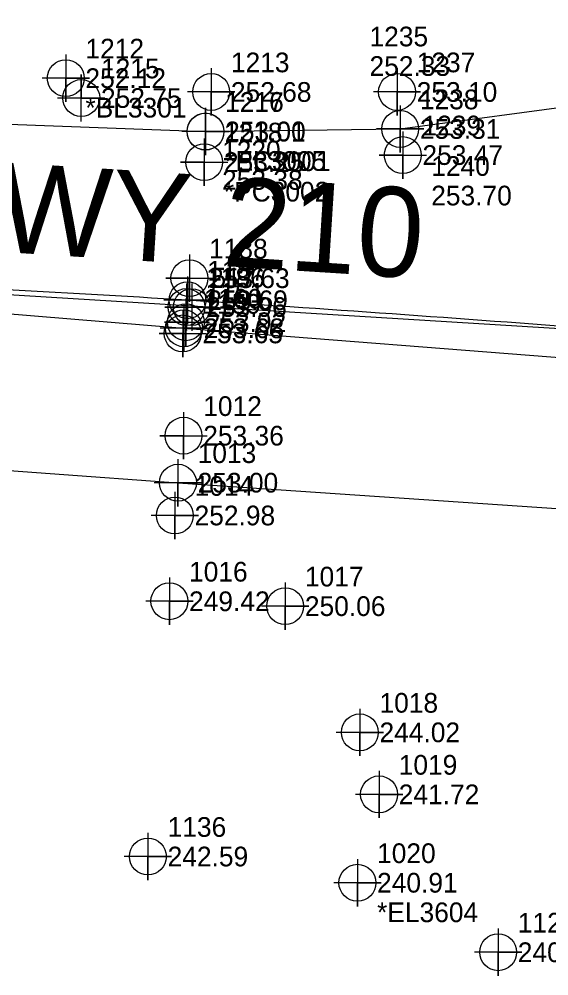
# Model space of a CAD drawing. Extents: x 2130621 to 2131998, y 642516 to 644503.
# Drawn here: x 2131075.1 to 2131142.4, y 643103 to 643224.5 of the extents above; entities that cross this region are included whole.
import ezdxf

# ---------------------------------------------------------------- set-up
doc = ezdxf.new("R2010")
doc.units = 0
for name, color, linetype in [('Cogo Default Point CELL', 7, 'Continuous'), ('COGO Default Point Number', 7, 'Continuous'), ('Exist Guardrail Cogo Comment', 7, 'Continuous'), ('Exist Guardrail Cogo Elevation', 7, 'Continuous'), ('Exist Guardrail Cogo Number', 7, 'Continuous'), ('Exist Guardrail Cogo Point CELL', 7, 'Continuous'), ('Exist Other Culture Fence Line Cogo Elevation', 7, 'Continuous'), ('Exist Other Culture Fence Line Cogo Number', 7, 'Continuous'), ('Exist Other Culture Fence Line Cogo Point CELL', 7, 'Continuous'), ('Exist Other Culture Sign Cogo Elevation', 7, 'Continuous'), ('Exist Other Culture Sign Cogo Number', 7, 'Continuous'), ('Exist Roads Curbs Cogo Elevation', 7, 'Continuous'), ('Exist Roads Curbs Cogo Number', 7, 'Continuous'), ('Exist Roads Curbs Cogo Point CELL', 7, 'Continuous'), ('Exist Roads EOP', 7, 'Continuous'), ('Exist Roads EOP Cogo Comment', 7, 'Continuous'), ('Exist Roads EOP Cogo Elevation', 7, 'Continuous'), ('Exist Roads EOP Cogo Number', 7, 'Continuous'), ('Exist Roads EOP Cogo Point CELL', 7, 'Continuous'), ('Exist Roads EOT Cogo Comment', 7, 'Continuous'), ('Exist Roads EOT Cogo Elevation', 7, 'Continuous'), ('Exist Roads EOT Cogo Number', 7, 'Continuous'), ('Exist Roads EOT Cogo Point CELL', 7, 'Continuous'), ('Exist Roads EOT Text', 7, 'Continuous'), ('Exist Roads Soil Cogo Comment', 7, 'Continuous'), ('Exist Roads Soil Cogo Elevation', 7, 'Continuous'), ('Exist Roads Soil Cogo Number', 7, 'Continuous'), ('Exist Roads Soil Cogo Point CELL', 7, 'Continuous'), ('Exist Vegetation Woods Line Cogo Comment', 7, 'Continuous'), ('Exist Vegetation Woods Line Cogo Elevation', 7, 'Continuous'), ('Exist Vegetation Woods Line Cogo Number', 7, 'Continuous'), ('Exist Vegetation Woods Line Cogo Point CELL', 7, 'Continuous'), ('Prop Horizontal Alignment', 7, 'Continuous')]:
    doc.layers.add(name, color=color, linetype=linetype)

msp = doc.modelspace()

# ---------------------------------------------------------------- linework, layer by layer
at = {"layer": 'Cogo Default Point CELL'}
for points in [[(2131097.03, 643190.9), (2131097.03, 643187.9)], [(2131094.03, 643187.9), (2131097.03, 643187.9)], [(2131097.03, 643187.9), (2131100.03, 643187.9)], [(2131097.03, 643187.9), (2131097.03, 643184.9)]]:
    msp.add_lwpolyline(points, dxfattribs=at)
msp.add_circle((2131097.03, 643187.9), 2.34, dxfattribs=at)
at = {"layer": 'Exist Guardrail Cogo Point CELL'}
for points in [[(2131081.04, 643219.97), (2131081.04, 643213.97), (2131081.04, 643216.97), (2131084.04, 643216.97), (2131078.04, 643216.97)], [(2131099.5, 643218.22), (2131099.5, 643212.22), (2131099.5, 643215.22), (2131102.5, 643215.22), (2131096.5, 643215.22)], [(2131123.08, 643218.22), (2131123.08, 643212.22), (2131123.08, 643215.22), (2131126.08, 643215.22), (2131120.08, 643215.22)], [(2131094.89, 643164.46), (2131094.89, 643158.46), (2131094.89, 643161.46), (2131097.89, 643161.46), (2131091.89, 643161.46)]]:
    msp.add_lwpolyline(points, dxfattribs=at)
for centre in [(2131081.04, 643216.97), (2131099.5, 643215.22), (2131123.08, 643215.22), (2131094.89, 643161.46)]:
    msp.add_circle(centre, 2.34, dxfattribs=at)
at = {"layer": 'Exist Other Culture Fence Line Cogo Point CELL'}
for points in [[(2131091.47, 643121.17), (2131091.47, 643115.17), (2131091.47, 643118.17), (2131094.47, 643118.17), (2131088.47, 643118.17)], [(2131135.91, 643109.02), (2131135.91, 643103.02), (2131135.91, 643106.02), (2131138.91, 643106.02), (2131132.91, 643106.02)]]:
    msp.add_lwpolyline(points, dxfattribs=at)
for centre in [(2131091.47, 643118.17), (2131135.91, 643106.02)]:
    msp.add_circle(centre, 2.34, dxfattribs=at)
at = {"layer": 'Exist Roads Curbs Cogo Point CELL'}
for points in [[(2131096.36, 643190.92), (2131096.36, 643184.92), (2131096.36, 643187.92), (2131093.63, 643187.92), (2131099.36, 643187.92)], [(2131096.29, 643188.99), (2131096.29, 643182.99), (2131096.29, 643185.99), (2131093.56, 643185.99), (2131099.29, 643185.99)]]:
    msp.add_lwpolyline(points, dxfattribs=at)
for centre in [(2131096.36, 643187.92), (2131096.29, 643185.99)]:
    msp.add_circle(centre, 2.34, dxfattribs=at)
at = {"layer": 'Exist Roads EOP'}
for points in [[(2131123.48, 643210.52), (2131148.04, 643213.86), (2131166.25, 643216.7)], [(2130999.39, 643215.45), (2131048.83, 643212.08), (2131098.77, 643210.18), (2131123.48, 643210.52)], [(2130999.32, 643193.17), (2131048.36, 643189.17), (2131096.04, 643185.22), (2131148.03, 643181.19), (2131197.86, 643177.88), (2131226.61, 643175.76)], [(2130997.26, 643172.43), (2131046.61, 643169.14), (2131095.28, 643165.62), (2131146.45, 643162.12), (2131188.44, 643158.22), (2131196.4, 643155.89)]]:
    msp.add_lwpolyline(points, dxfattribs=at)
for points in [[(2131166.25, 643216.7), (2131171.81, 643218.72), (2131182.37, 643223.97), (2131191.81, 643231.15), (2131200.5, 643239.7), (2131208.81, 643249.07), (2131216.07, 643259), (2131218.72, 643264.35), (2131220.54, 643270.1), (2131222.84, 643282.01), (2131224.36, 643293.92), (2131224.88, 643317.79), (2131222.06, 643367.67), (2131218.54, 643416.81), (2131214.32, 643466.35), (2131209.17, 643515.67), (2131202.79, 643565.15), (2131195.05, 643613.99), (2131186.4, 643662.48), (2131176.01, 643711.41), (2131164.62, 643759.89), (2131151.87, 643807.85), (2131137.86, 643855.41), (2131122.57, 643902.86), (2131105.96, 643949.49), (2131091.53, 643988.04)], [(2131226.91, 643179.17), (2131198.07, 643181.47), (2131148.43, 643185.15), (2131096.5, 643188.78), (2131047.67, 643191.53), (2130998.95, 643194.46)]]:
    msp.add_spline(points, degree=3, dxfattribs=at)
at = {"layer": 'Exist Roads EOP Cogo Point CELL'}
for points in [[(2131123.48, 643213.52), (2131123.48, 643207.52), (2131123.48, 643210.52), (2131126.48, 643210.52), (2131120.48, 643210.52)], [(2131098.77, 643213.18), (2131098.77, 643207.18), (2131098.77, 643210.18), (2131101.77, 643210.18), (2131095.77, 643210.18)], [(2131096.5, 643191.78), (2131096.5, 643185.78), (2131096.5, 643188.78), (2131099.5, 643188.78), (2131093.5, 643188.78)], [(2131096.04, 643188.22), (2131096.04, 643182.22), (2131096.04, 643185.22), (2131099.04, 643185.22), (2131093.04, 643185.22)], [(2131095.28, 643168.62), (2131095.28, 643162.62), (2131095.28, 643165.62), (2131098.28, 643165.62), (2131092.28, 643165.62)]]:
    msp.add_lwpolyline(points, dxfattribs=at)
for centre in [(2131098.77, 643210.18), (2131123.48, 643210.52), (2131096.5, 643188.78), (2131096.04, 643185.22), (2131095.28, 643165.62)]:
    msp.add_circle(centre, 2.34, dxfattribs=at)
at = {"layer": 'Exist Roads EOT Cogo Point CELL'}
for points in [[(2131123.81, 643210.21), (2131123.81, 643204.21), (2131123.81, 643207.21), (2131120.81, 643207.21), (2131126.81, 643207.21)], [(2131098.61, 643209.31), (2131098.61, 643203.31), (2131098.61, 643206.31), (2131095.61, 643206.31), (2131101.61, 643206.31)], [(2131096.73, 643194.58), (2131096.73, 643188.58), (2131096.73, 643191.58), (2131093.73, 643191.58), (2131099.73, 643191.58)], [(2131095.88, 643187.57), (2131095.88, 643181.57), (2131095.88, 643184.57), (2131092.88, 643184.57), (2131098.88, 643184.57)], [(2131095.99, 643174.59), (2131095.99, 643168.59), (2131095.99, 643171.59), (2131092.99, 643171.59), (2131098.99, 643171.59)]]:
    msp.add_lwpolyline(points, dxfattribs=at)
for centre in [(2131098.61, 643206.31), (2131123.81, 643207.21), (2131096.73, 643191.58), (2131095.88, 643184.57), (2131095.99, 643171.59)]:
    msp.add_circle(centre, 2.34, dxfattribs=at)
at = {"layer": 'Exist Roads Soil Cogo Point CELL'}
for points in [[(2131083.01, 643211.45), (2131083.01, 643217.45), (2131083.01, 643214.45), (2131086.01, 643214.45), (2131080.01, 643214.45)], [(2131098.77, 643207.21), (2131098.77, 643213.21), (2131098.77, 643210.21), (2131101.77, 643210.21), (2131095.77, 643210.21)]]:
    msp.add_lwpolyline(points, dxfattribs=at)
for centre in [(2131083.01, 643214.45), (2131098.77, 643210.21)]:
    msp.add_circle(centre, 2.34, dxfattribs=at)
at = {"layer": 'Exist Vegetation Woods Line Cogo Point CELL'}
for points in [[(2131094.19, 643153.57), (2131094.19, 643147.57), (2131094.19, 643150.57), (2131097.19, 643150.57), (2131091.19, 643150.57)], [(2131108.89, 643152.95), (2131108.89, 643146.95), (2131108.89, 643149.95), (2131111.89, 643149.95), (2131105.89, 643149.95)], [(2131118.36, 643136.93), (2131118.36, 643130.93), (2131118.36, 643133.93), (2131121.36, 643133.93), (2131115.36, 643133.93)], [(2131120.8, 643129.06), (2131120.8, 643123.06), (2131120.8, 643126.06), (2131123.8, 643126.06), (2131117.8, 643126.06)], [(2131118.05, 643117.84), (2131118.05, 643111.84), (2131118.05, 643114.84), (2131121.05, 643114.84), (2131115.05, 643114.84)]]:
    msp.add_lwpolyline(points, dxfattribs=at)
for centre in [(2131094.19, 643150.57), (2131108.89, 643149.95), (2131118.36, 643133.93), (2131120.8, 643126.06), (2131118.05, 643114.84)]:
    msp.add_circle(centre, 2.34, dxfattribs=at)
at = {"layer": 'Prop Horizontal Alignment'}
msp.add_line((2130998.32, 643194.18), (2131251.47, 643178.51), dxfattribs=at)

# ---------------------------------------------------------------- texts
at = {"layer": 'COGO Default Point Number'}
msp.add_text('517', height=2.5, dxfattribs=at).set_placement((2131099.53, 643190.4))
at = {"layer": 'Exist Guardrail Cogo Comment'}
msp.add_text('*BL3301', height=2.5, dxfattribs=at).set_placement((2131083.54, 643211.97))
at = {"layer": 'Exist Guardrail Cogo Elevation'}
for s, p in [('252.12', (2131083.54, 643215.72)), ('252.68', (2131102, 643213.97)), ('253.10', (2131125.58, 643213.97)), ('252.98', (2131097.39, 643160.21))]:
    msp.add_text(s, height=2.5, dxfattribs=at).set_placement(p)
at = {"layer": 'Exist Guardrail Cogo Number'}
for s, p in [('1212', (2131083.54, 643219.47)), ('1213', (2131102, 643217.72)), ('1237', (2131125.58, 643217.72)), ('1014', (2131097.39, 643163.96))]:
    msp.add_text(s, height=2.5, dxfattribs=at).set_placement(p)
at = {"layer": 'Exist Other Culture Fence Line Cogo Elevation'}
for s, p in [('242.59', (2131093.97, 643116.92)), ('240.13', (2131138.41, 643104.77))]:
    msp.add_text(s, height=2.5, dxfattribs=at).set_placement(p)
at = {"layer": 'Exist Other Culture Fence Line Cogo Number'}
for s, p in [('1136', (2131093.97, 643120.67)), ('1129', (2131138.41, 643108.52))]:
    msp.add_text(s, height=2.5, dxfattribs=at).set_placement(p)
at = {"layer": 'Exist Other Culture Sign Cogo Elevation'}
msp.add_text('252.33', height=2.5, dxfattribs=at).set_placement((2131119.59, 643217.26))
at = {"layer": 'Exist Other Culture Sign Cogo Number'}
msp.add_text('1235', height=2.5, dxfattribs=at).set_placement((2131119.59, 643221.01))
at = {"layer": 'Exist Roads Curbs Cogo Elevation'}
for s, p in [('253.96', (2131098.86, 643186.67)), ('253.92', (2131098.79, 643184.74))]:
    msp.add_text(s, height=2.5, dxfattribs=at).set_placement(p)
at = {"layer": 'Exist Roads Curbs Cogo Number'}
for s, p in [('1186', (2131098.86, 643190.42)), ('1161', (2131098.79, 643188.49))]:
    msp.add_text(s, height=2.5, dxfattribs=at).set_placement(p)
at = {"layer": 'Exist Roads EOP Cogo Comment'}
msp.add_text('*PC3001', height=2.5, dxfattribs=at).set_placement((2131101.27, 643205.18))
at = {"layer": 'Exist Roads EOP Cogo Elevation'}
for s, p in [('253.01', (2131101.27, 643208.93)), ('253.31', (2131125.98, 643209.27)), ('253.69', (2131099, 643187.53)), ('253.68', (2131098.54, 643183.97)), ('253.00', (2131097.78, 643164.37))]:
    msp.add_text(s, height=2.5, dxfattribs=at).set_placement(p)
at = {"layer": 'Exist Roads EOP Cogo Number'}
for s, p in [('1217', (2131101.27, 643212.68)), ('1238', (2131125.98, 643213.02)), ('1187', (2131099, 643191.28)), ('1160', (2131098.54, 643187.72)), ('1013', (2131097.78, 643168.12))]:
    msp.add_text(s, height=2.5, dxfattribs=at).set_placement(p)
at = {"layer": 'Exist Roads EOT Cogo Comment'}
msp.add_text('*PC3002', height=2.5, dxfattribs=at).set_placement((2131101.11, 643201.31))
at = {"layer": 'Exist Roads EOT Cogo Elevation'}
for s, p in [('253.47', (2131126.31, 643205.96)), ('253.25', (2131101.11, 643205.06)), ('253.38', (2131100.88, 643202.8)), ('253.70', (2131127.42, 643200.82)), ('253.63', (2131099.23, 643190.33)), ('253.65', (2131098.38, 643183.32)), ('253.36', (2131098.49, 643170.34))]:
    msp.add_text(s, height=2.5, dxfattribs=at).set_placement(p)
at = {"layer": 'Exist Roads EOT Cogo Number'}
for s, p in [('1239', (2131126.31, 643209.71)), ('1218', (2131101.11, 643208.81)), ('1220', (2131100.88, 643206.55)), ('1240', (2131127.42, 643204.57)), ('1188', (2131099.23, 643194.08)), ('1159', (2131098.38, 643187.07)), ('1012', (2131098.49, 643174.09))]:
    msp.add_text(s, height=2.5, dxfattribs=at).set_placement(p)
at = {"layer": 'Exist Roads EOT Text'}
msp.add_text('NC HWY 210 ', height=11.3735, rotation=356.3624, dxfattribs=at).set_placement((2131035.03, 643197.32))
at = {"layer": 'Exist Roads Soil Cogo Comment'}
msp.add_text('*EL3005', height=2.5, dxfattribs=at).set_placement((2131101.27, 643205.21))
at = {"layer": 'Exist Roads Soil Cogo Elevation'}
for s, p in [('252.75', (2131085.51, 643213.2)), ('253.00', (2131101.27, 643208.96))]:
    msp.add_text(s, height=2.5, dxfattribs=at).set_placement(p)
at = {"layer": 'Exist Roads Soil Cogo Number'}
for s, p in [('1215', (2131085.51, 643216.95)), ('1216', (2131101.27, 643212.71))]:
    msp.add_text(s, height=2.5, dxfattribs=at).set_placement(p)
at = {"layer": 'Exist Vegetation Woods Line Cogo Comment'}
msp.add_text('*EL3604', height=2.5, dxfattribs=at).set_placement((2131120.55, 643109.84))
at = {"layer": 'Exist Vegetation Woods Line Cogo Elevation'}
for s, p in [('249.42', (2131096.69, 643149.32)), ('250.06', (2131111.39, 643148.7)), ('244.02', (2131120.86, 643132.68)), ('241.72', (2131123.3, 643124.81)), ('240.91', (2131120.55, 643113.59))]:
    msp.add_text(s, height=2.5, dxfattribs=at).set_placement(p)
at = {"layer": 'Exist Vegetation Woods Line Cogo Number'}
for s, p in [('1016', (2131096.69, 643153.07)), ('1017', (2131111.39, 643152.45)), ('1018', (2131120.86, 643136.43)), ('1019', (2131123.3, 643128.56)), ('1020', (2131120.55, 643117.34))]:
    msp.add_text(s, height=2.5, dxfattribs=at).set_placement(p)

doc.saveas('drawing.dxf')
